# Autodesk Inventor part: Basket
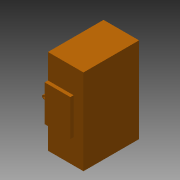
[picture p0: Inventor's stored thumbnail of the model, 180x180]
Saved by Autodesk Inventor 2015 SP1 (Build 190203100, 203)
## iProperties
Created: 2008-12
Part Number: Basket
Document SubType Name: Modeling
Designer: dwoollam
Density: 7.85 g/cm^3
Material: Steel
Appearance: Orange
Mass: 3.57207e+06 g
Surface Area: 158205 cm^2
Volume: 455040 cm^3
Dwg_Category: Clearance_Mewp
INSTALLATION: False
CIVIL_WORK: False
EARTHING: False
MOUNTING: False
Author: dwoollam
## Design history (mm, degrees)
sketch "Sketch1"
  geometry: L1 (-380, 595)-(-380, -595); L2 (-380, -595)-(380, -595); L3 (380, -595)-(380, 595); L4 (380, 595)-(-380, 595); L5 (-335, 595)-(340, 595); L6 (340, 595)-(340, -560); L7 (340, -560)-(-335, -560); L8 (-335, -560)-(-335, 595); L9 (-540, 795)-(-455, 795); L10 (-335, 675)-(-335, 185); L11 (-335, 185)-(-540, 185); L12 (-660, 305)-(-660, 675); L13 (-380, -665)-(170, -665); L14 (170, -665)-(170, -595); L15 (170, -595)-(-380, -595); L16 (-380, -595)-(-380, -665); A1 r 120 centre (-540, 305) between (-660, 305) and (-540, 185); A2 r 120 centre (-540, 675) between (-540, 795) and (-660, 675); A3 r 120 centre (-455, 675) between (-335, 675) and (-455, 795); 3 further points
  constraints: 32 end point, 7 parallel, 6 point on circle, 6 tangent, 4 perpendicular, 3 centre point, 3 horizontal, 2 equal radius, 2 horizontal alignment, 2 midpoint, 2 vertical, 2 vertical alignment
  dimensions: "d0" = 760 distance of L1.end L2.end; "d1" = 1190 distance of L2.end L3.end; "d2" = 675 distance of L6.end L7.end; "d3" = 1155 distance of L7.end L5.start; "d6" = 120 radius of A1; "d7" = 325 distance between parallel lines of L10 L12; "d8" = 610 distance between parallel lines of L9 L11; "d9" = 410 distance between parallel lines of L5 L11; "d10" = 45 distance of L5.start L1.start; "d12" = 70 distance of L13.end L14.end; "d27" = 550 distance of L13.start L13.end
extrude "Busket_P1" new body sketch "Sketch1" stored distance "d15" = 1830; taper "d16" = 0 deg
extrude "Busket_P2" cut sketch "Sketch1" stored distance "d17" = 1750; taper "d18" = 0 deg
extrude "Busket_P3" join sketch "Sketch1" stored distance "d19" = 775; taper "d20" = 0 deg
workplane "Work Plane1"
sketch "Sketch2"
  geometry: L1 (0, 0)-(0, 527.5) reference; L2 (550, 1302.5)-(0, 1302.5) reference; L3 (0, 527.5)-(550, 527.5) reference; L4 (550, 527.5)-(550, 1302.5) reference; L5 (0, 1302.5)-(0, 1830) reference; L6 (-120, 875)-(0, 875); L7 (0, 875)-(0, 955); L8 (-120, 955)-(0, 955); L9 (0, 527.5)-(0, 1302.5) reference; C1 r 25 at (-120, 915); A1 r 40 centre (-120, 915) between (-120, 955) and (-120, 875); 2 further points
  constraints: 6 end point, 2 centre point, 2 parallel, 2 point on circle, 2 tangent, 1 coincident, 1 collinear, 1 horizontal alignment, 1 midpoint, 1 vertical alignment
  dimensions: "d22" = 50 diameter of C1; "d23" = 40 radius of A1; "d24" = 120 distance from line of L7 C1.centre
extrude "Swivel Joint" join sketch "Sketch2" stored distance "d25" = 230; taper "d26" = 0 deg
body "Solid1"
node "Projected Loop1"
